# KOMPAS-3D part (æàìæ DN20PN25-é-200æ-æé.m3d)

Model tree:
1. Объединить компоненты:1  (labels: СЕНС DN20PN25-В-200С)
2. Эскиз:1
3. Операция выдавливания:1
     Расстояние 1 = 14
4. Фаска:1
     Угол = 45; Длина 1 = 2; Длина 2 = 2

Referenced files in D:\Савин\!СЕНСОР\3D для заказчика\!Новый перечень\СЕНС\4. СЕНС-В-200С\DN20\: СЕНС DN20PN25-В-200С.a3d
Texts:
  СЕНС DN20PN25-В-200С-СВ
  ООО НПП Сенсор
  СЕНС DN20PN25-В-200С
